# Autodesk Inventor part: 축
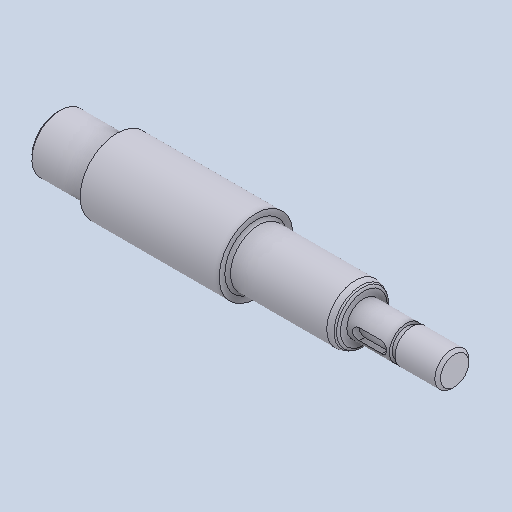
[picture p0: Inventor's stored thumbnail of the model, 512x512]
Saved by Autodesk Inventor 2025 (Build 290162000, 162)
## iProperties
Created: 2025-08
Part Number: 축
Material: 강철, 연강
Document SubType Name: Modeling
Designer: infra02
Density: 7.86 g/cm^3
Appearance: 기본값
Author: jhkim
Sending System: Autodesk Inventor 2026
Preprocessor: ST-DEVELOPER v20.1
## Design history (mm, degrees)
feature "솔리드2"
node "솔리드1"
